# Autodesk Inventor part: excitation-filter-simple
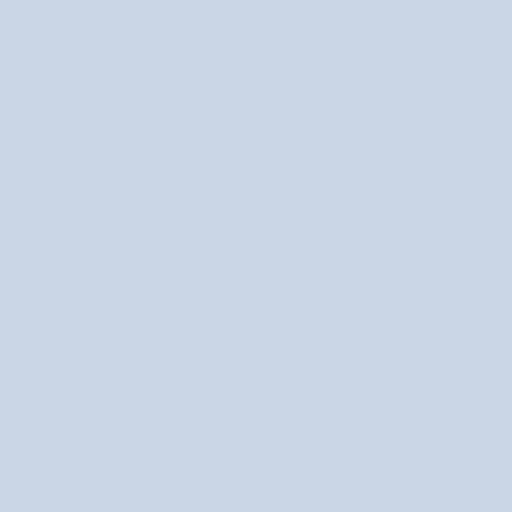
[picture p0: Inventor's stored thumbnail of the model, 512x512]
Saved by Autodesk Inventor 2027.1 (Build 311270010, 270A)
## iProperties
Created: 2026-08
Part Number: excitation-filter-simple
Material: Generic
Document SubType Name: Modeling
Designer: dunge
Density: 1 g/cm^3
Appearance: Default
Author: dunge
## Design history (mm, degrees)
sketch "Sketch1"
  geometry: C1 r 15.24 at (0, 0); 1 further point
  constraints: 1 centre point, 1 coincident
  dimensions: "d0" = 30.48 diameter of C1
extrude "Extrusion1" new body sketch "Sketch1" stored distance "d1" = 1.27; taper "d2" = 0 deg
body "Solid1"
node "Finishes"
node "Finish1" dims "Finish1_Area" = 158.09273
